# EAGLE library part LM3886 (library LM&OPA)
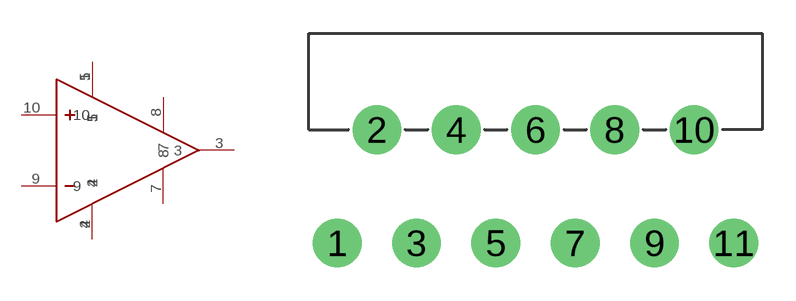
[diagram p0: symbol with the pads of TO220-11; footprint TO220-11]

Designator prefix -

## LM3886  [TO220-11]
1  1  pwr
2  2  pwr
3  3  out
4  4  pwr
5  5  pwr
7  7  pwr
8  8  in
9  9  in
10  10  in

## Footprint TO220-11 (pad centres in mm)
drill 1.016 pad 2.184 round: 1 -8.89,-2.54; 2 -7.112,2.54; 3 -5.334,-2.54; 4 -3.556,2.54; 5 -1.778,-2.54; 6 0,2.54; 7 1.778,-2.54; 8 3.556,2.54; 9 5.334,-2.54; 10 7.112,2.54; 11 8.89,-2.54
